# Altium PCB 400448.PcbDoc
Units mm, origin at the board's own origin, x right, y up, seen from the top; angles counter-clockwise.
Board outline 44.3 x 77.32 mm, 2 copper layers (Top Layer, Bottom Layer), stack 1.271 mm thick; 49 components, 38 nets, 169 pads, 325 vias.
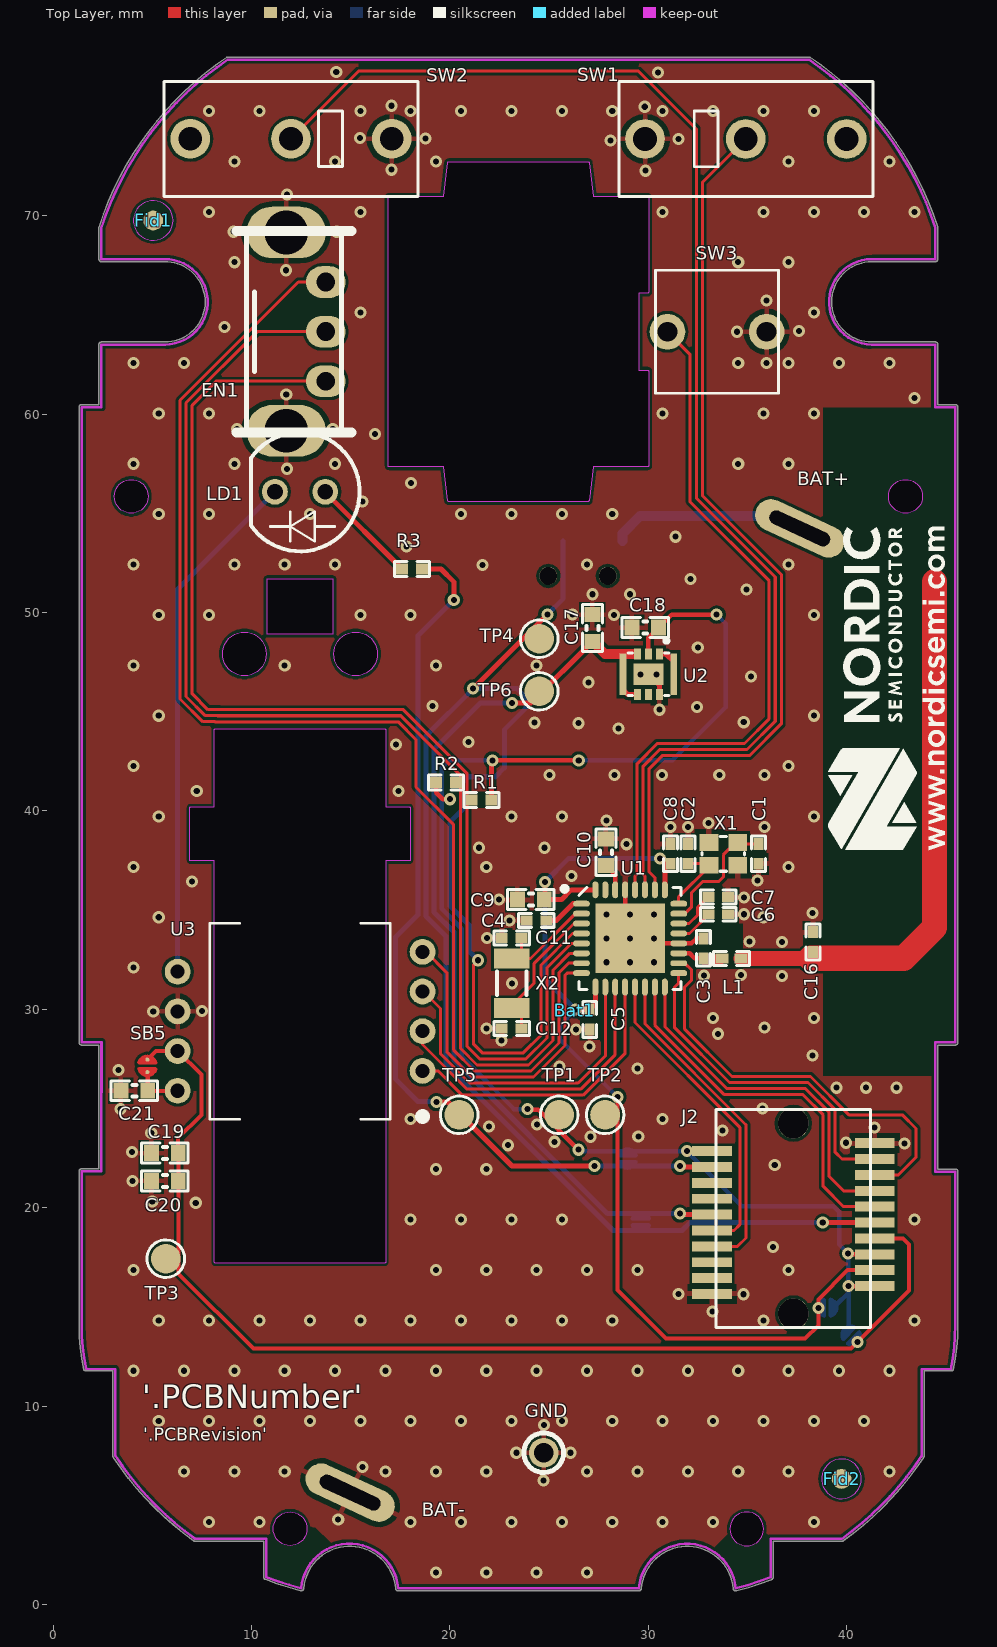
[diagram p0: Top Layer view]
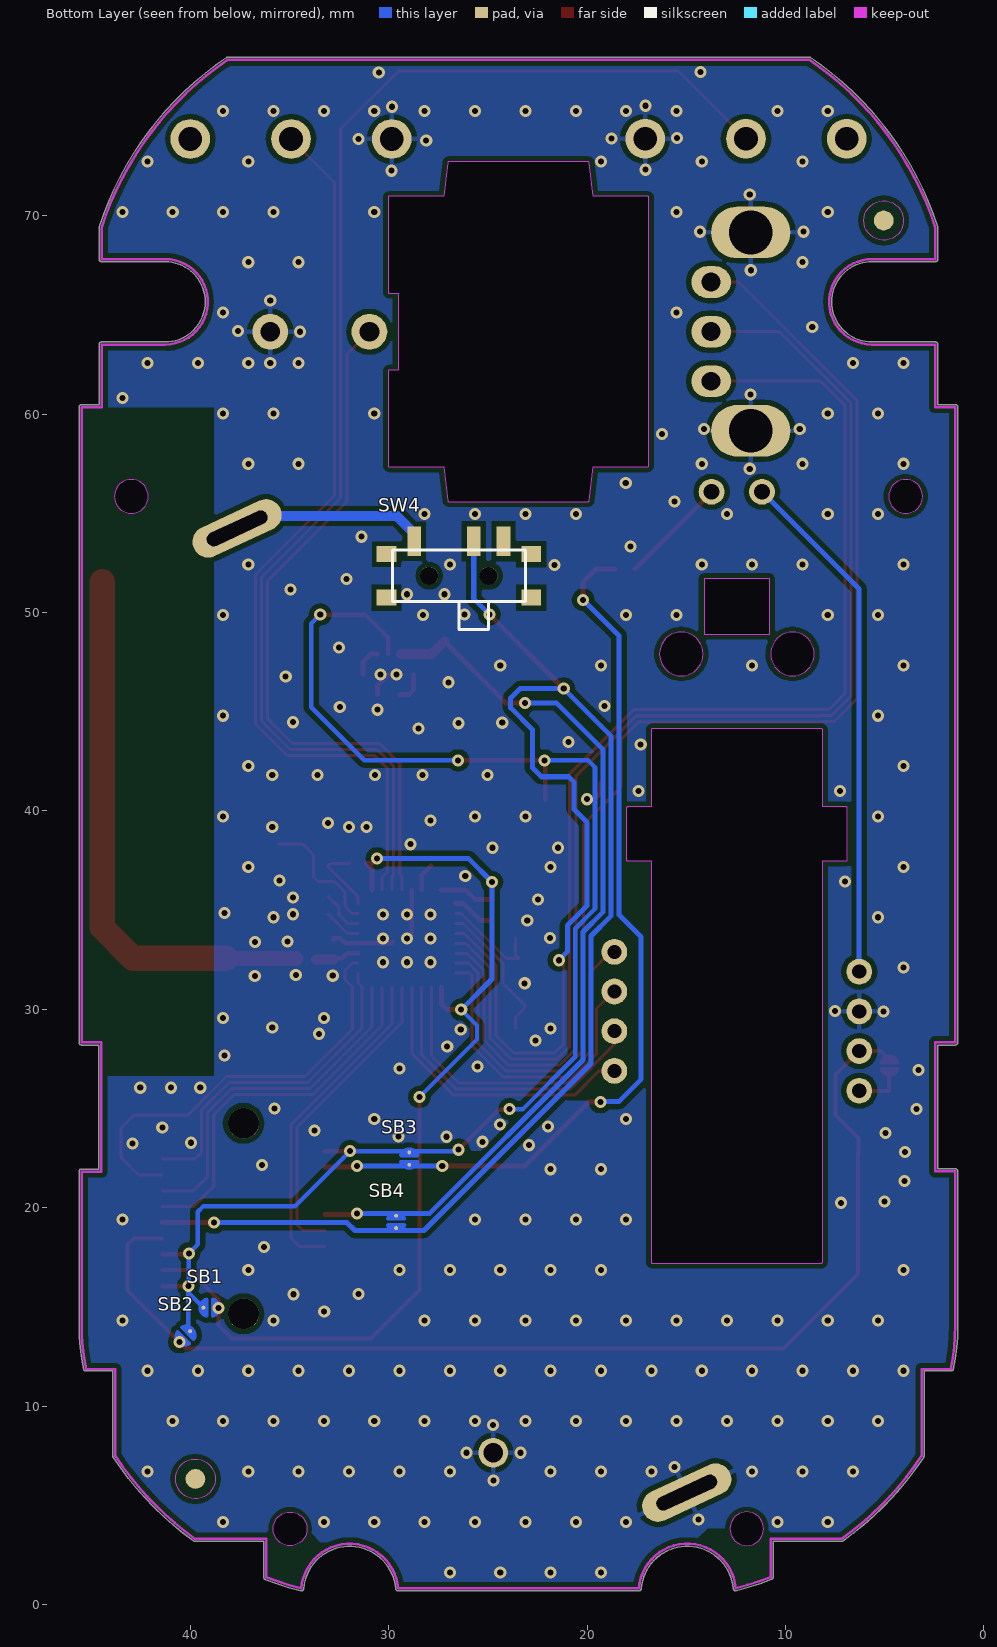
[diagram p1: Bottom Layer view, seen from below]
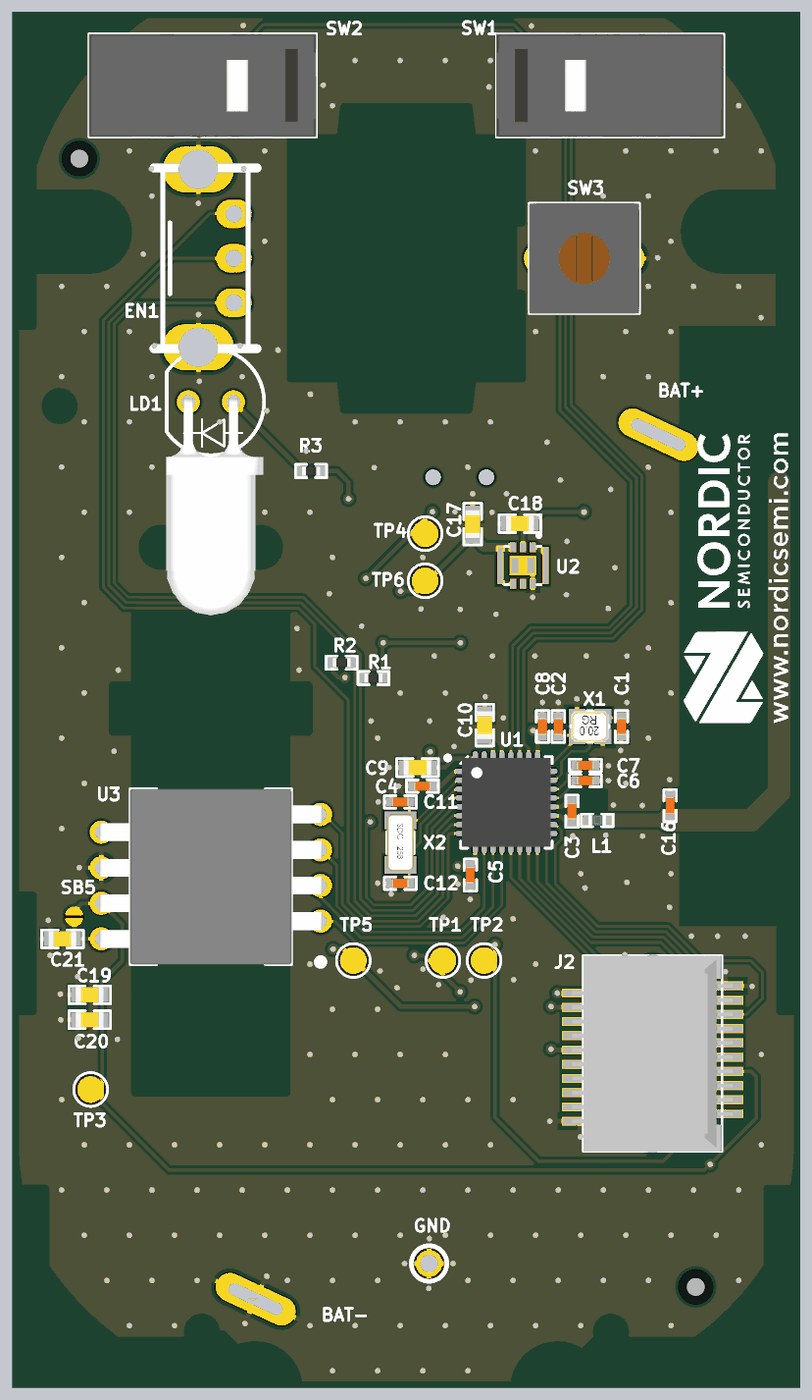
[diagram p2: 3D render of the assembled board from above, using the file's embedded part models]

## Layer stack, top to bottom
Top Solder: solder mask 0.0102, Solder Resist, Dk 3.5
Top Layer: signal copper 0.0356
Dielectric1: core 1.2, FR-4, Dk 4.8
Bottom Layer: signal copper 0.0356
Bottom Solder: solder mask 0.0102, Solder Resist, Dk 3.5

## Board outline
1.543,11.846 cw(c12.069,14.064) 1.312,14.064 1.312,21.831 cw(c1.439,21.831) 1.439,21.959 2.312,21.959 2.312,28.202 1.445,28.202 cw(c1.445,28.33) 1.344,28.251 cw(c1.439,28.336) 1.312,28.336 1.312,60.362 cw(c1.439,60.362) 1.439,60.489 2.312,60.489 2.312,63.514 cw(c2.44,63.514) 2.44,63.642 5.643,63.642 ccw(c5.643,65.666) 7.667,65.666 ccw(c5.643,65.666) 5.618,67.69 ccw(c5.643,65.666) 5.617,67.69 ccw(c5.616,67.753) 5.618,67.69 ccw(c5.616,67.753) 5.618,67.69 cw(c5.615,67.817) 5.617,67.69 cw(c5.615,67.817) 5.617,67.69 cw(c5.615,67.817) 5.617,67.69 cw(c5.643,65.666) 5.617,67.69 ccw(c5.616,67.753) 5.617,67.69 ccw(c5.643,65.666) 5.617,67.69 ccw(c5.643,65.666) 5.617,67.69 cw(c5.616,67.753) 5.617,67.69 cw(c5.615,67.753) 5.617,67.69 cw(c5.615,67.753) 5.616,67.689 cw(c5.616,67.753) 5.615,67.69 5.615,67.689 ccw(c5.616,67.753) 5.616,67.689 ccw(c5.616,67.753) 5.617,67.689 ccw(c5.615,67.817) 5.617,67.69 cw(c5.616,67.753) 5.617,67.69 cw(c5.616,67.753) 5.617,67.689 cw(c5.616,67.753) 5.616,67.689 cw(c5.615,67.753) 5.616,67.689 cw(c5.615,67.753) 5.615,67.689 2.44,67.689 cw(c2.44,67.817) 2.312,67.817 2.312,69.412 cw(c2.44,69.412) 2.319,69.452 cw(c17.952,64.365) 8.739,77.981 cw(c8.811,77.875) 8.811,78.003 38.103,78.003 cw(c38.103,77.875) 38.174,77.981 cw(c28.961,64.365) 44.595,69.452 cw(c44.473,69.412) 44.601,69.412 44.601,67.817 cw(c44.473,67.817) 44.473,67.69 41.271,67.689 cw(c41.271,67.753) 41.27,67.689 ccw(c41.271,65.666) 41.27,67.689 cw(c41.271,67.817) 41.27,67.689 ccw(c41.271,67.817) 41.271,67.689 cw(c41.27,67.753) 41.27,67.689 ccw(c41.271,65.666) 41.271,63.642 44.473,63.642 cw(c44.473,63.514) 44.601,63.514 44.601,60.489 45.474,60.489 cw(c45.474,60.362) 45.575,60.44 cw(c45.479,60.355) 45.607,60.355 45.607,28.33 cw(c45.479,28.33) 45.479,28.202 44.606,28.202 44.606,21.953 45.479,21.953 cw(c45.479,21.825) 45.607,21.825 45.607,14.058 cw(c45.543,14.058) 45.607,14.057 ccw(c34.848,14.058) 45.607,14.058 45.607,14.057 cw(c34.848,14.058) 45.376,11.839 cw(c45.313,11.852) 45.303,11.789 cw(c45.3,11.853) 45.3,11.789 43.906,11.789 43.906,7.483 cw(c43.778,7.483) 43.885,7.412 cw(c30.425,16.321) 39.834,3.206 cw(c39.76,3.31) 39.76,3.183 36.3,3.183 36.3,1.375 cw(c36.172,1.375) 36.218,1.255 cw(c30.425,16.321) 34.444,0.688 cw(c34.428,0.75) 34.428,0.686 cw(c34.412,0.748) 34.412,0.684 ccw(c34.412,0.812) 34.412,0.684 cw(c34.412,0.812) 34.285,0.802 cw(c34.412,0.812) 34.285,0.803 ccw(c34.348,0.807) 34.285,0.803 cw(c31.969,0.608) 34.285,0.802 cw(c31.969,0.608) 34.285,0.802 34.285,0.803 ccw(c31.969,0.608) 29.653,0.808 ccw(c31.969,0.608) 29.653,0.803 cw(c29.525,0.814) 29.51,0.687 17.394,0.687 cw(c17.394,0.815) 17.266,0.805 cw(c17.394,0.815) 17.266,0.805 cw(c14.95,0.615) 17.266,0.805 cw(c14.95,0.615) 17.266,0.805 ccw(c14.95,0.615) 12.634,0.809 ccw(c14.95,0.615) 12.634,0.809 ccw(c12.507,0.819) 12.634,0.809 cw(c12.507,0.819) 12.507,0.691 cw(c12.507,0.755) 12.491,0.693 cw(c12.491,0.757) 12.475,0.695 cw(c16.493,16.327) 10.701,1.262 cw(c10.747,1.381) 10.619,1.381 10.619,3.189 7.159,3.189 cw(c7.159,3.317) 7.084,3.213 cw(c16.493,16.327) 3.034,7.419 cw(c3.141,7.489) 3.013,7.489 3.013,11.795 1.625,11.795 cw(c1.625,11.859) 1.616,11.796 cw(c1.605,11.859)
cut-out: 15.25,46.816 cw(c15.25,47.917) 14.149,47.917 cw(c15.25,47.917) 15.25,49.018 cw(c15.25,47.917) 16.351,47.917 cw(c15.25,47.917)
cut-out: 3.941,55.007 cw(c3.941,55.858) 3.091,55.858 cw(c3.941,55.858) 3.941,56.709 cw(c3.941,55.858) 4.792,55.858 cw(c3.941,55.858)
cut-out: 19.891,55.65 19.691,57.345 16.952,57.345 cw(c16.952,57.409) 16.888,57.409 16.888,70.92 cw(c16.952,70.92) 16.952,70.984 19.691,70.984 19.891,72.679 cw(c19.954,72.671) 19.954,72.735 26.959,72.735 cw(c26.959,72.671) 27.023,72.679 27.222,70.984 29.962,70.984 cw(c29.962,70.92) 30.026,70.92 30.026,66.166 cw(c29.962,66.166) 29.962,66.102 29.525,66.102 29.525,62.227 29.962,62.227 cw(c29.962,62.163) 30.026,62.163 30.026,57.409 cw(c29.962,57.409) 29.962,57.345 27.222,57.345 27.023,55.65 cw(c26.959,55.658) 26.959,55.594 19.954,55.594 cw(c19.954,55.658)
cut-out: 9.646,46.816 cw(c9.646,47.917) 8.545,47.917 cw(c9.646,47.917) 9.646,49.018 cw(c9.646,47.917) 10.747,47.917 cw(c9.646,47.917)
cut-out: 8.131,17.268 8.131,37.48 6.944,37.48 cw(c6.944,37.544) 6.88,37.544 6.88,40.146 cw(c6.944,40.146) 6.944,40.21 8.131,40.21 8.131,44.089 cw(c8.195,44.089) 8.195,44.153 16.701,44.153 cw(c16.701,44.089) 16.765,44.089 16.765,40.21 17.952,40.21 cw(c17.952,40.146) 18.016,40.146 18.016,37.544 cw(c17.952,37.544) 17.952,37.48 16.765,37.48 16.765,17.268 cw(c16.701,17.268) 16.701,17.204 8.195,17.204 cw(c8.195,17.268)
cut-out: 34.12,3.811 ccw(c34.971,3.811) 34.971,2.96 ccw(c34.971,3.811) 35.822,3.811 ccw(c34.971,3.811) 34.971,4.661 ccw(c34.971,3.811)
cut-out: 11.948,2.966 cw(c11.948,3.817) 11.097,3.817 cw(c11.948,3.817) 11.948,4.668 cw(c11.948,3.817) 12.798,3.817 cw(c11.948,3.817)
cut-out: 42.972,55.007 cw(c42.972,55.858) 42.121,55.858 cw(c42.972,55.858) 42.972,56.709 cw(c42.972,55.858) 43.823,55.858 cw(c42.972,55.858)
cut-out: 10.797,48.913 10.797,51.715 14.099,51.715 14.099,48.913

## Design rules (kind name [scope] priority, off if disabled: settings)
Clearance ANT_Clerance [InNet('ANT')] p1: gap=0.127 ignorepadtopadclearanceinfootprint=FALSE except(0: Arc-Hole Track-Hole SMDPad-Hole THPad-Hole Via-Hole Fill-Hole Poly-Hole Region-Hole Text-Hole)
Clearance Polygon_Clearance [(InNamedPolygon('Top_Layer-GND')) or (InNamedPolygon('Bottom_Layer-GND'))] p2: gap=0.254 ignorepadtopadclearanceinfootprint=FALSE except(0: Arc-Hole Track-Hole SMDPad-Hole THPad-Hole Via-Hole Fill-Hole Poly-Hole Region-Hole Text-Hole)
Clearance [All] p3: gap=0.152 ignorepadtopadclearanceinfootprint=FALSE except(0: Arc-Hole Track-Hole SMDPad-Hole THPad-Hole Via-Hole Fill-Hole Poly-Hole Region-Hole Text-Hole)
ComponentClearance [All] p1 off: gap=0.254 collisioncheckmode=3 verticalgap=0.254 showdistances=FALSE
DiffPairsRouting [All] p1: maxlimit=0.15 minlimit=0.15 mostfreqgap=0.15 toplayer_minwidth=0.381 toplayer_maxwidth=0.381 toplayer_prefwidth=0.381 bottomlayer_minwidth=0.381 bottomlayer_maxwidth=0.381 bottomlayer_prefwidth=0.381 maxuncoupledlength=12.7
FabricationTestPointUsage TestPointUsage [All] p1: valid=0 allowmultiple=FALSE
FabricationTestpoint Testpoint [All] p1: side=3 testpointundercomponent=TRUE minsize=1.016 maxsize=2.54 preferedsize=1.524 minholesize=0 maxholesize=1.016 preferedholesize=0.813 testpointgrid=0.025 allowsidetop=TRUE allowsidebottom=TRUE usegrid=TRUE gridtolerance=0
Height [All] p1 off: minheight=0 maxheight=25.4 prefheight=12.7
HoleSize [All] p1: absolutevalues=TRUE maxlimit=5 minlimit=0.305 maxpercent=80.000 minpercent=20.000
MinimumAnnularRing [All] p1 off: minimumring=0.152
PolygonConnect PolygonConnect_1 [isVia and innet(gnd)] p1: connectstyle=Direct reliefconductorwidth=0.254 reliefentries=4 polygonreliefangle="90 Angle" airgapwidth=0.254
PolygonConnect [All] p2: connectstyle=Relief reliefconductorwidth=0.254 reliefentries=4 polygonreliefangle="90 Angle" airgapwidth=0.254
RoutingVias [All] p1: holewidth=0.305 width=0.61 viastyle="Through Hole" minholewidth=0.305 minwidth=0.61 maxholewidth=0.711 maxwidth=1.27
SilkToSolderMaskClearance SilkscreenOverComponentPads [IsPad] p1: minsilkscreentomaskgap=0.254 clearancetoexposedcopper=TRUE
SolderMaskExpansion [All] p1: expansion=0.076
Width [All] p1: maxlimit=2.54 minlimit=0.152 preferedwidth=0.152
23 further rules are at their usual default settings.

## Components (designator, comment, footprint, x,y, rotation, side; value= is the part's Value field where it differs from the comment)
Bat1 "" MORFFLUOA_Battery_Spring 26.308,29.943 r0 top locked
C1 "12pF" CAPC1005X04L 35.564,37.842 r270 top
C2 "12pF" CAPC1005X04L 32.008,37.842 r90 top
C3 "0.8pF" CAPC1005X04L 32.778,33.075 r270 top
C4 "100nF" CAPC1005X04L 24.363,34.489 r180 top
C5 "100nF" CAPC1005X04L 27.055,29.486 r270 top
C6 "N.C." CAPC1005X04L 33.532,34.794 r180 top
C7 "100pF" CAPC1005X04L 33.532,35.658 r0 top
C8 "100nF" CAPC1005X04L 31.119,37.842 r90 top
C9 "4.7µF" CAPC1608X06L 24.083,35.531 r180 top
C10 "1.0µF" CAPC1608X06L 27.868,37.918 r270 top
C11 "12pF" CAPC1005X04L 23.118,33.6 r180 top
C12 "12pF" CAPC1005X04L 23.118,29.028 r180 top
C16 "1.2pF" CAPC1005X04L 38.304,33.392 r90 top
C17 "10µF" CAPC1608X06L 27.19,49.222 r270 top
C18 "10µF" CAPC1608X06L 29.851,49.247 r0 top
C19 "10µF" CAPC1608X06L 5.633,22.756 r0 top
C20 "100nF" CAPC1608X06L 5.633,21.354 r0 top
C21 "4.7µF" CAPC1608X06L 4.098,25.896 r0 top
EN1 "Scroll wheel encoder" M01_Scroll_Wheel_Encoder 13.748,64.164 r270 top locked
Fid1 "Fiducial mark" Fiducial 5.048,69.766 r0 top
Fid2 "Fiducial mark" Fiducial 39.744,6.332 r0 top
GND "TP" TESTPAD-TH 24.733,7.649 r0 top
J2 "Card Edge, 0.8mm" 10056847-101LF 37.316,19.453 r90 top
L1 "3.9nH" INDC1005X04L 34.2,32.567 r0 top
LD1 "LED" LED_5MM_RA 12.452,56.09 r180 top locked
R1 "1M0" RESC1005X04L 21.601,40.56 r0 top
R2 "1M0" RESC1005X04L 19.811,41.432 r180 top
R3 "4R7" RESC1005X04L 18.093,52.202 r0 top
SB1 "Solderbridge" Solderbridge#1 39.026,14.961 r180 bottom
SB2 "Solderbridge" Solderbridge#1 40.236,13.554 r315 bottom
SB3 "Solderbridge" Solderbridge#1 28.964,22.477 r270 bottom
SB4 "Solderbridge" Solderbridge#1 29.626,19.283 r90 bottom
SB5 "Solderbridge" Solderbridge#2 4.752,27.152 r270 top
SW1 "SPDT" D2F-F 29.842,73.875 r0 top locked
SW2 "SPDT" D2F-F 17.072,73.882 r180 top locked
SW3 "EVQ-P0E07K" EVQP0E07K 33.471,64.157 r0 top locked
SW4 "CUS-12TB" CUS-12B 26.462,51.853 r180 bottom locked
TP1 "Ø1.5mm,SMD" TP_SMD_Ø1.5mm 25.513,24.683 r0 top
TP2 "Ø1.5mm,SMD" TP_SMD_Ø1.5mm 27.828,24.683 r0 top
TP3 "Ø1.5mm,SMD" TP_SMD_Ø1.5mm 5.685,17.433 r0 top
TP4 "Ø1.5mm,SMD" TP_SMD_Ø1.5mm 24.512,48.683 r0 top
TP5 "Ø1.5mm,SMD" TP_SMD_Ø1.5mm 20.472,24.683 r0 top
TP6 "Ø1.5mm,SMD" TP_SMD_Ø1.5mm 24.512,46.033 r0 top
U1 "nRF52810-QCAA" Nordic_QFN50P500X500X90-33N 29.087,33.575 r0 top locked
U2 "XCL101" CL-2025 30.014,46.889 r270 top
U3 "PAW3212" PAW3212DB-TJDT 12.454,28.899 r90 top locked
X1 "32MHz" BT-XTAL_2016 33.786,37.842 r180 top
X2 "32.768kHz" XTAL_3215 23.118,31.314 r270 top

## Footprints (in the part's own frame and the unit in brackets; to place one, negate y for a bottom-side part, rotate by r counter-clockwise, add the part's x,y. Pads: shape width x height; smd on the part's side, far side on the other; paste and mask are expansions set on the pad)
10056847-101LF [mm]
  rect 0.5x2 smd paste-0.05 mask+0.025: 1(-3.4,-4.1) 2(-2.6,-4.1) 3(-1.8,-4.1) 4(-1,-4.1) 5(-0.2,-4.1) 6(0.6,-4.1) 7(1.4,-4.1) 8(2.2,-4.1) 9(3,-4.1) 10(3.8,-4.1) 11(3.4,4.1) 12(2.6,4.1) 13(1.8,4.1) 14(1,4.1) 15(0.2,4.1) 16(-0.6,4.1) 17(-1.4,4.1) 18(-2.2,4.1) 19(-3,4.1) 20(-3.8,4.1)
  round 1.55 hole 1.55 unplated mask+0: ""(-4.8,0) ""(4.8,0)
  silkscreen extent -5.5,-3.9 5.5,3.9, body extent -5.5,-4.5 5.5,4.53, height 5.28
BT-XTAL_2016 [mm] "Crystal 2.0 x 1.6 mm"
  rect 0.95x0.85 smd: 1(-0.725,-0.575) 2(0.725,-0.575) 3(0.725,0.575) 4(-0.725,0.575)
  silkscreen extent -1.08,-0.88 1.08,0.88, body extent -1.05,-0.85 1.05,0.85, height 0.56
CAPC1005X04L [mm] "Chip Capacitor, 2-Leads, Body 1.0x0.5mm, IPC High Density"
  rect 0.6x0.5 smd: 1(-0.5,0) 2(0.5,0)
  silkscreen extent -0.9,-0.35 0.9,0.35, body extent -0.51,-0.25 0.51,0.25, height 0.5
CAPC1608X06L [mm] "Chip Capacitor, 2-Leads, Body 1.6x0.8mm, IPC High Density"
  rect 0.75x0.8 smd: 1(-0.675,0) 2(0.675,0)
  silkscreen extent -1.17,-0.5 1.17,0.5, body extent -0.8,-0.43 0.8,0.43, height 0.8
CL-2025 [mm]
  rect 0.55x0.35 smd paste-0.025 mask+0.076: 1(-1.025,0.55) 2(-1.025,0) 3(-1.025,-0.55) 4(1.025,-0.55) 5(1.025,0) 6(1.025,0.55)
  rect 2.1x0.35 smd paste-0.038 mask+0.076: 7(0,1.275) 8(0,-1.275)
  rect 1.1x1.5 smd paste-5 mask+0.076: 9(0,0)
  silkscreen extent -1.8,-1.02 1.07,1.02, body extent -1,-1.25 1.01,1.25, height 1
CUS-12B [mm] "Slide Switches - SPDT, SMD, ON-ON"
  rect 1x0.8 smd: 0(-3.65,-1.1) 0(-3.65,1.1) 0(3.65,-1.1) 0(3.65,1.1)
  round 0.9 hole 0.9 unplated: 0(-1.5,0) 0(1.5,0)
  rect 0.7x1.5 smd: 1(2.25,1.75) 2(0.75,1.75) 3(-2.25,1.75)
  silkscreen extent -3.35,-2.7 3.35,1.3, body extent -3.85,-2.75 3.85,2.2, height 1.4
D2F-F [mm]
  round 2 hole 1.2: 1(10.16,0) 2(0,0) 3(5.08,0)
  silkscreen extent -1.32,-2.9 11.48,2.9, body extent -1.32,-2.9 11.48,2.9, height 7
EVQP0E07K [mm]
  round 1.8 hole 1: 1(-2.5,0) 2(2.5,0)
  silkscreen extent -3.1,-3.1 3.1,3.1, body extent -3.1,-3.1 3.1,3.1, height 7.5
Fiducial [mm] "Fiducial Mark"
  round 1 smd paste+0 mask+0.5: 0(0,0)
  round 1 smd far side paste+0 mask+0.5: 0(0,0)
  Top Layer keep-out circle w0.01: c0,0 r1
  Bottom Layer keep-out circle w0.01: c0,0 r1
INDC1005X04L [mm] "Chip Inductor, 2-Leads, Body 1.0x0.5mm, IPC High Density"
  rect 0.65x0.5 smd: 1(-0.475,0) 2(0.475,0)
  silkscreen extent -0.9,-0.35 0.9,0.35, body extent -0.5,-0.3 0.5,0.3, height 0.5
LED_5MM_RA [mm]
  round 1.3 hole 0.8: 1(1.27,0) 2(-1.27,0)
  silkscreen extent -3,-3 2.48,3, body extent -2.95,-0.25 2.5,12, height 5.95
M01_Scroll_Wheel_Encoder [mm]
  oval 1.6x2 hole 0.95: 1(-2.5,0) 2(0,0) 3(2.5,0)
  oval 2.6x4 hole 2.2: 4(-5,-2) 5(5,-2)
  silkscreen extent -5.08,-4.5 5.08,1.3
MORFFLUOA_Battery_Spring [mm] "Edge Mount Battery Holder Suitable for 1xAAA"
  oval 4.8x1.6 hole 0.7 slot 3.3 at 155 deg rot 155: 1(11.333,24.304) 2(-11.333,-24.304)
Nordic_QFN50P500X500X90-33N [mm] "QFN32 5x5x0.85mm, 0.5mm pitch - Medium Density"
  oval 0.85x0.3 smd mask+0.076: 1(-2.45,1.75) 2(-2.45,1.25) 3(-2.45,0.75) 4(-2.45,0.25) 5(-2.45,-0.25) 6(-2.45,-0.75) 7(-2.45,-1.25) 8(-2.45,-1.75) 17(2.45,-1.75) 18(2.45,-1.25) 19(2.45,-0.75) 20(2.45,-0.25) 21(2.45,0.25) 22(2.45,0.75) 23(2.45,1.25) 24(2.45,1.75)
  oval 0.3x0.85 smd mask+0.076: 9(-1.75,-2.45) 10(-1.25,-2.45) 11(-0.75,-2.45) 12(-0.25,-2.45) 13(0.25,-2.45) 14(0.75,-2.45) 15(1.25,-2.45) 16(1.75,-2.45) 25(1.75,2.45) 26(1.25,2.45) 27(0.75,2.45) 28(0.25,2.45) 29(-0.25,2.45) 30(-0.75,2.45) 31(-1.25,2.45) 32(-1.75,2.45)
  rect 3.5x3.5 smd: 33(0,0)
  silkscreen extent -3.42,-2.57 2.57,2.62, body extent -2.5,-2.5 2.5,2.5, height 0.9
PAW3212DB-TJDT [mm] "Ultra Low Power Wireless Mouse Sensor"
  round 1.3 hole 0.71: 1(-2,-6.172) 2(0,-6.172) 3(2,-6.172) 4(4,-6.172) 5(3,6.172) 6(1,6.172) 7(-1,6.172) 8(-3,6.172)
  silkscreen extent -4.55,-6.42 5.45,4.55, body extent -4.45,-6.3 5.45,6.3, height 3.18
RESC1005X04L [mm] "Chip Resistor, 2-Leads, Body 1.0x0.5mm, IPC High Density"
  rect 0.6x0.55 smd: 1(-0.5,0) 2(0.5,0)
  silkscreen extent -0.87,-0.38 0.88,0.38, body extent -0.5,-0.25 0.5,0.25, height 0.3
Solderbridge#1 [mm]
  round 0.2 smd paste-10: 1(-0.312,0) 2(0.312,0)
  Top Layer region: 0.077,0.432 0.152,0.505 0.271,0.467 0.335,0.424 0.409,0.351 0.462,0.292 0.521,0.193 0.549,0.099 0.544,-0.122 0.518,-0.193 0.434,-0.33 0.351,-0.411 0.259,-0.469 0.157,-0.5 0.107,-0.483 0.077,-0.43
  Top Layer region: -0.077,-0.432 -0.152,-0.505 -0.271,-0.467 -0.335,-0.424 -0.409,-0.351 -0.462,-0.292 -0.521,-0.193 -0.549,-0.099 -0.544,0.122 -0.518,0.193 -0.434,0.33 -0.351,0.411 -0.259,0.469 -0.157,0.5 -0.107,0.483 -0.077,0.43
  Top Layer lines w0.152: 0.153,-0.431 ccw(c0.042,0) 0.153,0.431 ; -0.153,-0.431 cw(c-0.042,0) -0.153,0.431
Solderbridge#2 [mm]
  round 0.2 smd paste-10: 1(-0.312,0) 2(0.312,0)
  Top Layer region: 0.077,0.432 0.152,0.505 0.271,0.467 0.335,0.424 0.409,0.351 0.462,0.292 0.521,0.193 0.549,0.099 0.544,-0.122 0.518,-0.193 0.434,-0.33 0.351,-0.411 0.259,-0.469 0.157,-0.5 0.107,-0.483 0.077,-0.43
  Top Layer region: -0.077,-0.432 -0.152,-0.505 -0.271,-0.467 -0.335,-0.424 -0.409,-0.351 -0.462,-0.292 -0.521,-0.193 -0.549,-0.099 -0.544,0.122 -0.518,0.193 -0.434,0.33 -0.351,0.411 -0.259,0.469 -0.157,0.5 -0.107,0.483 -0.077,0.43
  Top Layer lines w0.152: 0.153,-0.431 ccw(c0.042,0) 0.485,-0.046 ccw(c0.042,0) 0.153,0.431 ; -0.153,-0.431 cw(c-0.042,0) -0.461,0.149 cw(c-0.042,0) -0.153,0.431
TESTPAD-TH [mm]
  round 1.5 hole 1: 1(0,0)
  silkscreen extent -1,-1 1,1
TP_SMD_Ø1.5mm [mm]
  round 1.5 smd paste-5: 1(0,0)
  silkscreen extent -0.95,-0.95 0.95,0.95
XTAL_3215 [mm] "XTAL SMD 3.2 x 1.5 mm"
  rect 1x1.8 smd: 1(-1.25,0) 2(1.25,0)
  silkscreen extent -0.6,-0.75 0.6,0.75, body extent -1.6,-0.75 1.6,0.75, height 0.81

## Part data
Bat1: library part "MORFFLOUA Battery Spring", "Battery Spring, 1xAA", Part number IPS=N.A.
C1 C2 C11 C12: library part C0402-12p, "Capacitor, NP0, ±2%"
C3: library part C0402-0.8p, "Capacitor, NP0, ±5%"
C4 C5 C8: library part C0402-100n, "Capacitor, X7R, ±10%"
C6: library part C0402-N.C., "Not mounted"
C7: library part C0402-100p, "Capacitor, NP0, ±5%"
C9: library part C0603-4µ7, "Capacitor, X5R, ±10%"
C10: library part C0603-1µ0, "Capacitor, X7R, ±10%"
C16: library part C0402-1.2p, "Capacitor, NP0, ±0.1pF", Part number IPS=00000005410
C17 C18 C19: library part C0603-10µ, "Capacitor, X5R, ±20%", Part number IPS=00000007785
C20: library part C0603-100n, "Chip Cap 0603", Part number IPS=N.A.
C21: library part C0603-4µ7, "Capacitor, X5R, ±10%", Part number IPS=00000007783
EN1: library part "M01_Scroll_wheel_encoder, 9mm", "Scroll wheel encoder, 9mm", Part number IPS=N.A.
Fid1 Fid2: library part Fid-Mark, "Fiducial Mark", Part number IPS=N.A.
GND: library part "Testpoint TH", "Testpoint, through hole", Part number IPS=N.A.
J2: library part 10056847-101LF, "0.8mm pitch, dual edge, right angle, SMD, card edge connector", Manufacturer=FCI, Part number IPS=N.A., Supplier Part Number 1=609-4943-1-ND
L1: library part L0402-3n9, "High frequency chip inductor ±5%"
LD1: library part 7383M-RNW3-APSB, "LED, Red, 5mm, Vf=2.0", Manufacturer=Everlight, Part number IPS=N.A.
R1 R2: library part R0402-1M0, "Resistor, ±1%, 0.063W", Part number IPS=00000006807
R3: library part R0402-4R7, "Resistor, ±1%, 0.063W", Part number IPS=N.A.
SB1 SB2 SB3 SB4 SB5: Part number IPS=N.A.
SW1 SW2: library part D2F-F, "SWITCH SNAP ACTION SPDT 1A 125V", Manufacturer=Omron, Part number IPS=N.A., Supplier Part Number 1=SW503-ND
SW3: "Switch tactile, SPST-NO, 0.05A, 30V", Manufacturer="Panasonic - ECG", Part number IPS=N.A., Supplier Part Number 1=P10843S-ND
SW4: "Low-profile slide switch, SPDT, ON-ON", Manufacturer="Copal Electronics Inc", Part number IPS=N.A., Supplier Part Number 1=563-1102-1-ND
TP1 TP2 TP3 TP4 TP5 TP6: library part TP_SMD_Ø1.5MM, "1.0mm circular SMD testpad", Manufacturer="Nordic Semiconductor", Part number IPS=N.A.
U1: library part nRF52810-QCAAD0, "Multi-protocol Bluetooth Low Energy, ANT and 2.4GHz proprietary system-on-chip", Manufacturer="Nordic Semiconductor", Part number IPS=N.A.
U2: library part XCL101A211ER-G, "Inductor Built-in Step-up “micro DC/DC” Converter, VOUT=2.1V, 100mA", Manufacturer="Torex Semiconductor", Part number IPS=N.A., Supplier Part Number 1=893-1206-1-ND
U3: library part PAW3212DB-TJDT, "Ultra Low Power Wireless Mouse Sensor", Manufacturer="Pixart Imaging inc", Part number IPS=N.A.
X1: library part XTAL_SMD2016_32MHz_8pF_General, "XTAL SMD 2016, 32MHz, Cl=8pF, Total Tol: ±40ppm"
X2: library part XTAL_SMD3215_32.768kHz_9pF_General, "XTAL SMD 3215, 32.768kHz, Cl=9pF, Total Tol: ±50ppm"

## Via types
v1: diameter 0.61, hole 0.305, Top Layer to Bottom Layer, tented both sides, 325 vias

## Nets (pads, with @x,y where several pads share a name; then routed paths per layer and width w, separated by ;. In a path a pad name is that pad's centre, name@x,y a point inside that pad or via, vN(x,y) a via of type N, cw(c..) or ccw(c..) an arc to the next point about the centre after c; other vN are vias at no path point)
ANT: C16.1 L1.2 | length 27.9
  Top Layer w0.762: L1.2@34.683,32.573 37.308,32.573 ; 37.308,32.572 38.304,32.573
  Top Layer w1.27: 38.19,32.573 42.879,32.573 44.439,34.132 44.439,51.554
BAT+: Bat1.1 SW4.3 | length 9.9
  Bottom Layer w0.508: SW4.3 28.712,53.985 29.591,54.864 37.023,54.864 Bat1.1@37.641,54.246
DEC1: C4.1 U1.1 | length 2.1
  Top Layer w0.254: C4.1 25.379,34.489 26.214,35.325 U1.1
DEC2: C6.2 U1.21 | length 1.9
  Top Layer w0.152: U1.21 32.08,33.825 C6.2@33.049,34.794
DEC3: C7.1 U1.22 | length 2.3
  Top Layer w0.152: U1.22 32.059,34.325 32.495,34.762 32.495,35.147 C7.1@33.032,35.683
DEC4: C10.2 U1.30 | length 1.4
  Top Layer w0.229: C10.2 28.337,36.774 U1.30
GND: Bat1.2 C1.2 C2.2 C3.1 C4.2 C5.2 C6.1 C7.2 C8.2 C9.2 C10.1 C11.2 C12.2 C16.2 C17.1 C18.1 C19.1 C20.1 C21.1 EN1.4 EN1.5 GND.1 J2.10 J2.20 SW1.2 SW2.2 SW3.2 U1.20 U1.29 U1.33 U2.6 U2.9 U3.6 X1.2 X1.4 | length 6.9
  Top Layer w0.229: U1.29 28.837,33.825 v1(29.087,33.575) ; U1.33@29.787,33.4 29.862,33.325 U1.20 32.183,33.325 32.433,33.575 C3.1 ; C3.1@32.778,33.515 C3.1@32.786,33.515
  Top Layer w0.254: U2.9 30.564,46.339 U2.6
  other v1: 19.298,1.622 21.838,1.622 24.378,1.622 26.918,1.622 7.868,4.162 10.408,4.162 18.028,4.162 20.568,4.162 23.108,4.162 25.648,4.162 28.188,4.162 30.728,4.162 33.268,4.162 38.348,4.162 14.375,4.277 24.715,6.25 6.598,6.702 9.138,6.702 11.678,6.702 16.758,6.702 19.298,6.702 21.838,6.702 26.918,6.702 29.458,6.702 31.998,6.702 34.538,6.702 37.078,6.702 42.158,6.702 15.6,6.933 23.35,7.65 26.082,7.65 24.747,9.05 5.328,9.242 7.868,9.242 10.408,9.242 12.948,9.242 15.488,9.242 18.028,9.242 20.568,9.242 23.108,9.242 25.648,9.242 28.188,9.242 30.728,9.242 33.268,9.242 35.808,9.242 38.348,9.242 40.888,9.242 4.058,11.782 6.598,11.782 9.138,11.782 11.678,11.782 14.218,11.782 16.758,11.782 19.298,11.782 21.838,11.782 24.378,11.782 26.918,11.782 29.458,11.782 31.998,11.782 34.538,11.782 37.078,11.782 39.618,11.782 42.158,11.782 5.328,14.322 7.868,14.322 10.408,14.322 12.948,14.322 15.488,14.322 18.028,14.322 20.568,14.322 23.108,14.322 25.648,14.322 28.188,14.322 35.808,14.322 43.428,14.322 33.25,14.775 31.527,15.65 34.799,15.638 4.058,16.862 19.298,16.862 21.838,16.862 24.378,16.862 26.918,16.862 29.458,16.862 37.078,16.862 36.282,18.025 18.028,19.402 20.568,19.402 23.108,19.402 25.648,19.402 43.428,19.402 7.193,20.25 5,20.309 4.008,21.342 19.298,21.942 21.838,21.942 36.38,22.15 3.975,22.8 22.933,23.152 42.917,23.229 39.975,23.275 25.269,23.325 27.093,23.578 29.5,23.6 4.95,23.775 33.75,23.885 41.414,24.053 21.975,24.1 24.389,24.201 18.028,24.482 30.728,24.482 3.4,24.975 35.753,25 39.5,26.05 40.975,26.05 42.525,26.05 3.3,26.944 29.458,27.022 25.53,27.115 38.275,27.681 27.05,28.122 22.6,28.425 33.515,28.769 26.369,28.979 21.842,29.029 35.869,29.079 33.268,29.562 38.348,29.562 5.05,29.901 7.5,29.925 23.143,31.314 36.75,31.675 32.821,31.695 34.683,31.729 4.058,32.102 27.887,32.375 29.087,32.375 30.287,32.375 36.736,33.4 35.107,33.423 27.887,33.575 30.287,33.575 21.872,33.6 23.016,34.489 5.328,34.642 35.808,34.642 27.887,34.775 29.087,34.775 30.287,34.775 34.827,34.794 38.275,34.85 22.483,35.531 34.827,35.632 7,36.453 35.513,36.496 26.141,36.725 4.058,37.182 21.838,37.182 37.078,37.182 21.467,38.147 24.769,38.147 28.909,38.325 31.119,39.188 32.008,39.188 35.869,39.188 33.049,39.392 27.893,39.519 5.328,39.722 23.108,39.722 25.648,39.722 38.348,39.722 7.243,41.016 17.418,41.016 25.023,41.805 28.3,41.805 30.687,41.805 33.583,41.805 35.869,41.805 4.058,42.262 37.078,42.262 17.296,43.35 20.942,43.48 28.5,44.15 26.488,44.424 24.275,44.45 34.817,44.475 5.328,44.802 38.348,44.802 30.564,45.105 32.465,45.25 19.125,45.3 26.995,46.488 35.192,46.775 29.614,46.889 30.414,46.889 4.058,47.342 11.678,47.342 19.298,47.342 24.378,47.342 32.5,48.25 5.328,49.882 7.868,49.882 15.488,49.882 18.028,49.882 28.275,49.882 38.348,49.882 26.189,49.913 27.19,50.926 29.087,50.926 34.958,51.166 32.125,51.7 21.65,52.4 4.058,52.422 9.138,52.422 11.678,52.422 14.218,52.422 26.918,52.422 37.078,52.422 17.816,53.325 31.375,53.825 5.328,54.962 7.868,54.962 12.948,54.962 20.568,54.962 23.108,54.962 25.648,54.962 28.188,54.962 15.6,55.591 18.05,56.525 11.8,57.25 4.058,57.502 9.138,57.502 14.218,57.502 34.538,57.502 37.078,57.502 16.228,59 9.278,59.25 14.099,59.25 5.328,60.042 7.868,60.042 30.728,60.042 35.808,60.042 38.348,60.042 43.428,60.825 11.755,61 4.058,62.582 6.598,62.582 34.538,62.582 35.971,62.582 37.078,62.582 39.618,62.582 42.158,62.582 34.475,64.157 37.6,64.2 8.65,64.4 15.488,65.122 38.348,65.122 35.971,65.736 11.748,67.257 9.138,67.662 34.538,67.662 37.078,67.662 9.1,69.2 14.302,69.2 7.868,70.202 15.488,70.202 30.728,70.202 35.808,70.202 38.348,70.202 40.888,70.202 43.428,70.202 11.8,71.075 29.865,72.275 17.05,72.325 9.138,72.742 14.218,72.742 19.298,72.742 37.078,72.742 42.158,72.742 28.108,73.8 31.525,73.872 18.775,73.9 15.475,73.925 7.868,75.282 10.408,75.282 15.488,75.282 18.028,75.282 20.568,75.282 23.108,75.282 25.648,75.282 28.188,75.282 30.728,75.282 33.268,75.282 35.808,75.282 38.348,75.282 29.825,75.5 17.05,75.55 30.5,77.225 14.275,77.25
NetC3_2: C3.2 L1.1 U1.19 | length 2.2
  Top Layer w0.229: U1.19 32.087,32.825 32.337,32.575 C3.2 ; C3.2@32.778,32.515 C3.2@32.786,32.515
  Top Layer w0.508: C3.2@32.778,32.52 L1.1@33.675,32.52
NetC21_2: C21.2 SB5.2 U3.8 | length 2.5
  Top Layer w0.203: 4.706,26.667 4.706,26.793 SB5.2 ; 4.773,26.692 C21.2 6.279,25.896 U3.8
NetLD1_1: LD1.1 U3.5 | length 26.2
  Bottom Layer w0.254: U3.5 6.282,51.19 LD1.1
NetLD1_2: LD1.2 R3.1 | length 5.5
  Top Layer w0.254: LD1.2 13.722,56.072 R3.1
NetU2_1: U2.1 U2.7 | length 1.5
  Top Layer w0.254: U2.1 30.895,47.914 31.289,47.52 U2.7
P0.00/XL1: C11.1 U1.2 X2.1 | length 5.3
  Top Layer w0.152: C11.1 23.618,32.76 23.423,32.564 24.066,32.564 26.327,34.825 U1.2
P0.01/XL2: C12.1 U1.3 X2.2 | length 7.2
  Top Layer w0.152: C12.1 23.618,29.59 23.143,30.064 23.143,30.222 24.25,31.329 24.25,32.317 26.258,34.325 U1.3
P0.04/AIN2: J2.5 SB4.1 SW4.2 TP4.1 U1.4 | length 88.5
  Top Layer w0.152: v1(21.425,32.475) 21.2,32.25 21.2,28.236 21.628,27.809 23.709,27.809 24.591,28.691 24.591,32.228 26.189,33.825 U1.4
  Top Layer w0.254: v1(21.175,46.175) 21.187,46.175 v1(24.925,49.913) ; v1(38.8,19.25) 39.499,19.25 39.502,19.253 J2.5
  Bottom Layer w0.254: v1(21.425,32.475) 20.994,32.906 20.994,34.226 20,35.22 20,39.425 20.65,40.075 20.65,41.45 20.925,41.725 22.3,41.725 22.75,42.175 22.75,44.1 23.85,45.2 23.85,45.7 23.375,46.175 v1(21.175,46.175) 21.175,46.163 18.8,43.788 18.8,34.7 19.8,33.7 19.8,27.275 28.222,18.853 31.703,18.853 32.1,19.25 v1(38.8,19.25) ; v1(24.925,49.913) 25.712,50.7 SW4.2
P0.05/AIN3: EN1.3 R1.1 U1.5 | length 61.6
  Top Layer w0.152: EN1.3 8.226,61.664 7.01,60.447 7.01,45.903 7.803,45.11 8.421,45.11 8.426,45.105 17.653,45.105 20.875,41.882 20.875,40.585 20.875,28.13 21.501,27.504 23.84,27.504 24.896,28.56 24.896,32.101 26.12,33.325 U1.5
P0.06: EN1.2 R2.1 U1.6 | length 63.4
  Top Layer w0.152: EN1.2 10.295,64.164 6.705,60.574 6.705,45.776 7.676,44.805 8.295,44.805 8.3,44.8 17.526,44.8 20.55,41.776 20.55,41.307 20.55,28.024 21.375,27.199 23.967,27.199 25.201,28.433 25.201,31.975 26.051,32.825 U1.6
P0.09: EN1.1 U1.7 | length 65.3
  Top Layer w0.152: EN1.1 12.364,66.664 6.4,60.7 6.4,45.65 7.55,44.5 8.169,44.5 8.174,44.495 17.4,44.495 18.3,43.595 18.3,41.2 20.175,39.325 20.175,27.968 21.249,26.894 24.093,26.894 25.506,28.307 25.506,31.849 25.982,32.325 U1.7
P0.10: U1.8 U3.4 | length 17.2
  Top Layer w0.152: U3.4 18.801,32.899 19.85,31.85 19.85,27.862 21.123,26.589 24.219,26.589 25.81,28.181 25.81,31.723 25.913,31.825 U1.8
P0.12: U1.10 U3.3 | length 16.5
  Top Layer w0.152: U3.3 18.67,30.899 19.525,30.044 19.525,27.756 20.996,26.285 26.472,26.285 27.837,27.649 U1.10
P0.14: U1.11 U3.2 | length 15.4
  Top Layer w0.152: U3.2 18.626,28.224 20.87,25.98 26.599,25.98 28.337,27.718 U1.11
P0.15: U1.12 U3.1 | length 14.9
  Top Layer w0.152: U3.1 19.401,26.899 20.625,25.675 26.725,25.675 28.837,27.787 U1.12
P0.16: J2.16 U1.13 | length 15.7
  Top Layer w0.152: U1.13 29.337,29.338 34.619,24.056 34.619,19.144 34.328,18.853 J2.16
P0.18: J2.17 U1.14 | length 16.7
  Top Layer w0.152: U1.14 29.837,29.269 34.906,24.2 34.925,24.2 34.925,18.476 34.502,18.053 J2.17
P0.20: J2.6 U1.15 | length 18.9
  Top Layer w0.152: U1.15 30.337,29.2 33.837,25.7 37.8,25.7 38.818,24.682 38.818,21.082 39.847,20.053 J2.6
P0.21: J2.7 U1.16 | length 17.9
  Top Layer w0.152: U1.16 30.837,29.138 33.97,26.005 37.926,26.005 39.123,24.808 39.123,21.577 39.847,20.853 J2.7
P0.25: SW1.3 U1.26 | length 45.9
  Top Layer w0.152: U1.26 30.337,36.642 30.052,36.927 30.052,42.135 30.708,42.79 35.103,42.79 36.71,44.397 36.71,51.921 32.73,55.901 32.73,71.683 SW1.3
P0.28/AIN4: SW2.3 U1.27 | length 68.4
  Top Layer w0.152: SW2.3 15.41,77.3 29.5,77.3 32.425,74.375 32.425,55.775 36.405,51.795 36.405,44.524 34.976,43.095 30.582,43.095 29.747,42.261 29.747,36.801 29.837,36.711 U1.27
P0.30/AIN6: SW3.1 U1.28 | length 35.6
  Top Layer w0.152: U1.28 29.337,36.721 29.443,36.826 29.443,42.387 30.455,43.4 34.85,43.4 36.1,44.65 36.1,51.6 32.099,55.601 32.099,63.029 SW3.1
SWDCLK: J2.9 U1.17 | length 16.9
  Top Layer w0.152: U1.17 31.537,31.325 31.337,31.125 31.337,29.069 34.096,26.31 38.05,26.31 ; 38.053,26.31 39.428,24.934 39.428,22.791 39.766,22.453 J2.9
SWDIO: J2.8 U1.18 | length 21.6
  Top Layer w0.152: U1.18 31.847,32.325 32.191,31.982 32.191,31.479 31.837,31.125 31.837,29 34.223,26.614 38.175,26.614 ; 38.179,26.614 40.111,24.683 42.811,24.683 43.5,23.993 43.5,22.543 42.611,21.653 J2.8
VBAT: C17.2 J2.15 SB4.2 TP6.1 U2.3 U2.4 U2.8 | length 46.9
  Top Layer w0.254: v1@22.95,45.475 22.975,45.45 v1(23.125,45.45) 24.094,45.45 C17.2 ; U2.8 28.739,46.109 28.984,45.864 U2.4 ; U2.3 U2.3@29.464,48.006 ; v1(31.6,19.7) 31.647,19.653 J2.15
  Top Layer w0.508: C17.2 27.824,47.914 U2.3@29.375,47.914
  Bottom Layer w0.254: v1(23.125,45.45) 21.55,45.45 19.206,43.106 19.206,34.9 20.206,33.9 20.206,27.443 27.95,19.7 29.386,19.7 29.866,19.7 v1(31.6,19.7)
VDD_LED: J2.12 R3.2 SB3.2 TP5.1 | length 45.9
  Top Layer w0.254: R3.2 18.595,52.2 19.554,52.2 20.2,51.554 v1(20.2,50.64) ; v1(19.327,25.327) 19.908,25.327 23.135,22.1 v1(27.3,22.1) ; v1(31.6,22.1) 31.647,22.053 J2.12
  Bottom Layer w0.254: v1(19.327,25.327) 19.303,25.35 18.4,25.35 17.272,26.478 17.272,33.647 18.394,34.769 18.394,48.833 v1(20.2,50.64) ; v1(27.3,22.1) 28.671,22.1 29.257,22.1 v1(31.6,22.1)
VDD_nRF: C5.1 C8.1 C9.1 J2.2 SB1.2 TP2.1 U1.9 U1.25 U1.32 | length 52.9
  Top Layer w0.203: v1(28.452,25.581) 28.452,15.848 30.9,13.4 37.9,13.4 38.575,14.075 38.575,15.375 40.053,16.853 J2.2
  Top Layer w0.254: v1(24.794,36.42) 24.794,35.567 C9.1 25.633,35.531 26.127,36.025 U1.32 ; v1(26.344,29.986) C5.1 27.337,30.268 U1.9 ; v1(30.586,37.614) 30.857,37.342 C8.1 30.837,37.06 U1.25
  Bottom Layer w0.203: v1(26.344,29.986) 26.344,29.981 25.55,29.187 25.55,28.483 v1(28.452,25.581)
  Bottom Layer w0.254: v1(26.344,29.986) 24.794,31.535 v1(24.794,36.42) 25.988,37.614 v1(30.586,37.614)
  other v1: 38.575,14.95
VDD_Sensor: C19.2 C20.2 J2.4 SB2.2 SB5.1 TP3.1 U3.7 | length 57.7
  Top Layer w0.203: SB5.1 4.901,27.613 5.187,27.899 U3.7 7.475,26.706 7.475,24.673 6.308,23.506 C19.2 ; C19.2@6.333,22.756 6.333,16.667 10.1,12.9 40.229,12.9 v1(40.554,13.225) 43.158,15.829 43.158,18.142 42.847,18.453 J2.4
VREG: C18.2 J2.1 J2.3 J2.11 R1.2 R2.2 SB1.1 SB2.1 SB3.1 TP1.1 U2.2 | length 77.3
  Top Layer w0.229: R2.2 19.311,40.925 19.644,40.593 v1(20,40.593) ; v1@19.926,40.674 v1@20,40.6 ; R1.2 22.101,42.501 v1(22.15,42.55) ; v1@22.25,42.55 v1(26.5,42.55) ; v1(23.909,24.975) 23.934,24.95 24.455,24.95 v1(26.48,22.925) ; U2.2 30.014,48.735 C18.2 31.181,49.902 v1(33.45,49.902) ; v1(31.95,22.85) 33.212,22.85 J2.11 ; v1(40.075,17.7) 40.122,17.653 J2.3 ; v1(40.1,16.05) 40.103,16.053 J2.1
  Bottom Layer w0.229: v1(20,40.593) 19.607,40.593 19.6,40.6 ; v1(22.15,42.55) 19.95,42.55 19.6,42.2 19.6,40.6 ; v1(23.909,24.975) 23.232,24.975 20.6,27.606 20.6,34.063 19.6,35.063 19.6,40.6 ; v1(26.48,22.925) 26.48,22.87 26.5,22.85 v1(31.95,22.85) 34.734,20.066 39.359,20.066 39.625,19.8 39.625,18.15 v1(40.075,17.7) 40.075,16.075 v1(40.1,16.05) 40.1,15.722 ; v1(26.5,42.55) 31.225,42.55 33.9,45.225 33.9,49.452 v1(33.45,49.902) ; 39.488,15.11 40.1,15.722 ; SB2.1@39.997,13.793 40.1,13.896 40.1,15.722
XC1: C1.1 U1.23 X1.1 | length 6.6
  Top Layer w0.152: U1.23 31.847,34.825 32.191,35.168 32.191,35.886 32.749,36.445 33.557,36.445 33.786,36.674 33.786,37.791 34.337,38.342 C1.1
XC2: C2.1 U1.24 X1.3 | length 3.7
  Top Layer w0.152: U1.24 31.537,35.669 33.061,37.193 X1.3@33.061,37.195 ; C2.1@31.957,37.342 C2.1 32.914,37.342 X1.3@33.061,37.195 ; X1.3 X1.3@33.061,37.195
pads on no net: Fid1.0 Fid2.0 J2. J2.13 J2.14 J2.18 J2.19 SW1.1 SW2.1 SW4.0 SW4.1 U1.31 U2.5

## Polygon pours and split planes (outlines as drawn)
GND on Top Layer "Top Layer-GND" (solid, remove dead copper, pour order 41): 1.439,14.626 1.439,21.831 2.44,21.831 2.44,28.336 1.439,28.336 1.439,60.362 2.44,60.362 2.44,63.514 5.643,63.514 ccw(c5.643,65.666) 5.615,67.817 2.44,67.817 2.44,69.412 cw(c17.952,64.365) 8.811,77.875 38.103,77.875 cw(c28.961,64.365) 44.473,69.412 44.473,67.817 41.271,67.817 ccw(c41.271,65.666) 41.271,63.514 44.473,63.514 44.473,60.362 45.474,60.362 45.474,28.336 45.474,0.815 17.394,0.815 ccw(c14.95,0.615) 12.507,0.819 cw(c16.493,16.327) 10.747,1.381 10.747,3.317 7.159,3.317 cw(c16.494,16.327) 3.141,7.489 3.141,11.323 1.784,11.323 cw(c17.452,14.626)
GND on Bottom Layer "Bottom_Layer-GND" (solid, remove dead copper, pour order 42): 1.439,14.626 1.439,21.831 2.44,21.831 2.44,28.336 1.439,28.336 1.439,60.362 2.44,60.362 2.44,63.514 5.643,63.514 ccw(c5.643,65.666) 5.615,67.817 2.44,67.817 2.44,69.412 cw(c17.952,64.365) 8.811,77.875 38.103,77.875 cw(c28.961,64.365) 44.473,69.412 44.473,67.817 41.271,67.817 ccw(c41.271,65.666) 41.271,63.514 44.473,63.514 44.473,60.362 45.474,60.362 45.474,28.336 45.474,0.815 17.394,0.815 ccw(c14.95,0.615) 12.507,0.819 cw(c16.493,16.327) 10.747,1.381 10.747,3.317 7.159,3.317 cw(c16.494,16.327) 3.141,7.489 3.141,11.323 1.784,11.323 cw(c17.452,14.626)

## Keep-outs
Keep-Out Layer:
  lines w0.013: 1.439,14.626 1.439,21.831 2.44,21.831 2.44,28.336 1.439,28.336 1.439,60.362 2.44,60.362 2.44,63.514 5.643,63.514 ccw(c5.643,65.666) 5.615,67.817 2.44,67.817 2.44,69.412 cw(c17.952,64.365) 8.811,77.875 38.103,77.875 cw(c28.961,64.365) 44.473,69.412 44.473,67.817 41.271,67.817 ccw(c41.271,65.666) 41.271,63.514 44.473,63.514 44.473,60.362 45.474,60.362 45.474,28.336 44.473,28.336 ; 3.141,11.323 3.141,7.489 ccw(c16.493,16.327) 7.159,3.317 10.747,3.317 10.747,1.381 ccw(c16.493,16.327) 12.507,0.819 cw(c14.95,0.615) 17.394,0.815 22.456,0.815
  lines w0.127: 1.439,14.626 1.439,21.831 ; 1.445,60.355 1.445,28.33 2.446,28.33 2.446,25.828 ; 1.67,11.864 cw(c12.144,14.072) 1.439,14.072 1.439,21.831 ; 1.675,11.859 3.141,11.859 ; 3.141,11.823 3.141,7.489 ; 22.454,0.815 29.519,0.815 ; 29.525,0.814 cw(c31.969,0.608) 34.412,0.812 ccw(c30.425,16.321) 36.172,1.375 36.172,3.31 39.76,3.31 ccw(c30.425,16.321) 43.778,7.483 43.778,11.853 45.248,11.853 ccw(c34.73,14.071) 45.479,14.071 45.479,21.825 44.479,21.825 44.479,28.33 45.479,28.33 45.479,60.355 ; 45.474,28.336 45.474,60.362 ; 1.439,21.831 2.44,21.831 ; 1.439,21.831 2.44,21.831 ; 1.439,28.336 1.439,60.362 ; 1.439,28.336 2.44,28.336 ; 1.439,28.336 1.439,60.362 ; 1.439,28.336 2.44,28.336 ; 1.439,60.362 2.44,60.362 ; 1.439,60.362 2.44,60.362 ; 2.44,21.831 2.44,28.336 ; 2.44,21.831 2.44,28.336 ; 2.44,60.362 2.44,63.514 ; 2.44,60.362 2.44,63.514 ; 2.44,63.514 5.643,63.514 ; 2.44,63.514 5.643,63.514 ; 2.44,67.817 2.44,69.412 ; 2.44,67.817 5.615,67.817 ; 2.44,67.817 2.44,69.412 ; 2.44,67.817 5.615,67.817 ; 2.44,69.412 cw(c17.952,64.365) 8.811,77.875 ; 2.44,69.412 cw(c17.952,64.365) 8.811,77.875 ; 3.141,7.489 ccw(c16.493,16.327) 7.159,3.317 ; 3.141,7.489 ccw(c16.493,16.327) 7.159,3.317 ; 5.615,67.817 cw(c5.643,65.666) 5.643,63.514 ; 5.615,67.817 cw(c5.643,65.666) 5.643,63.514 ; 7.159,3.317 7.159,3.317 ; 7.159,3.317 10.747,3.317 ; 7.159,3.317 10.747,3.317 ; 8.811,77.875 38.103,77.875 ; 8.811,77.875 38.103,77.875 ; 10.747,1.381 ccw(c16.493,16.327) 12.507,0.819 ; 10.747,1.381 ccw(c16.493,16.327) 12.507,0.819 ; 10.747,1.381 10.747,3.317 ; 10.747,1.381 10.747,3.317 ; 12.507,0.819 cw(c14.95,0.615) 17.394,0.815 ; 12.507,0.819 cw(c14.95,0.615) 17.394,0.815 ; 12.507,0.819 12.507,0.819 ; 17.394,0.815 22.456,0.815 17.394,0.815 ; 38.103,77.875 cw(c28.961,64.365) 44.473,69.412 ; 38.103,77.875 cw(c28.961,64.365) 44.473,69.412 ; 41.271,63.514 cw(c41.271,65.666) 41.271,67.817 ; 41.271,63.514 cw(c41.271,65.666) 41.271,67.817 ; 41.271,63.514 44.473,63.514 ; 41.271,63.514 44.473,63.514 ; 41.271,67.817 41.271,67.817 ; 41.271,67.817 44.473,67.817 ; 41.271,67.817 44.473,67.817 ; 44.473,60.362 45.474,60.362 ; 44.473,60.362 44.473,63.514 ; 44.473,60.362 45.474,60.362 ; 44.473,60.362 44.473,63.514 ; 44.473,67.817 44.473,69.412 ; 44.473,67.817 44.473,69.412

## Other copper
Top Layer:
  pour cut-out: 34.802,32.025 32.059,32.025 32.059,34.337 34.802,34.337
  pour cut-out: 12.75,3.904 13.221,3.904 14.375,2.75 14.05,2.425 13.35,2.425 12.175,3.6
  pour cut-out: 34.119,3.675 33.119,2.675 32.85,2.675 32.85,2.625 33.35,2.125 34.65,3.425 34.922,3.425
  pour cut-out: 14.525,66.025 14.475,65.975 14.475,64.739 13.907,64.739 13.746,64.9 13.775,64.929 13.775,66.183
Bottom Layer:
  pour cut-out: 19.825,25.425 21,25.425 21.175,25.6 20.875,25.9 19.85,25.9 19.625,25.675
  pour cut-out: 25.953,23 25.803,22.85 25.321,22.85 25.321,22.8 25.775,22.346 26.054,22.625 26.15,22.625
  pour cut-out: 19.5,26.925 20.05,27.475 19.925,27.475 19.775,27.625 19.375,27.225 19.375,27.2
  pour cut-out: 32.775,3.15 33.45,3.15 34.3,4 34.725,3.575 34.725,3.05 33.702,3.05 32.827,2.175
  pour cut-out: 14.6,3.175 13.925,3.85 12.711,3.85 12.711,3.785 12.526,3.6 13.651,2.475 14.325,2.475
Multi-Layer:
  pour cut-out: 38.803,60.355 46.515,60.355 46.487,26.621 38.806,26.621

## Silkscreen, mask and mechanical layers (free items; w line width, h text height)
Top Overlay:
  drawing of 43 lines, arcs and shapes, not listed
  text "'.PCBNumber'" at 4.5,9.486 h2.03
  text "'.PCBRevision'" at 4.551,8.266 h0.64
Board Outline:
  circle w0.127: c34.971,3.811 r0.851
  circle w0.127: c15.25,47.917 r1.101
  circle w0.127: c9.646,47.917 r1.101
  circle w0.127: c11.948,3.817 r0.851
  circle w0.127: c3.941,55.858 r0.851
  circle w0.127: c42.972,55.858 r0.851
  lines w0.127: 1.605,11.859 cw(c12.069,14.064) 1.375,14.064 1.375,21.831 cw(c1.439,21.831) 1.439,21.895 2.376,21.895 2.376,28.266 1.445,28.266 cw(c1.445,28.33) 1.393,28.292 cw(c1.439,28.336) 1.375,28.336 1.375,60.362 cw(c1.439,60.362) 1.439,60.425 2.376,60.425 2.376,63.514 cw(c2.44,63.514) 2.44,63.578 5.643,63.578 ccw(c5.643,65.666) 7.731,65.666 ; 1.625,11.859 3.077,11.859 3.077,7.489 ccw(c3.141,7.489) 3.087,7.454 ccw(c16.493,16.327) 7.122,3.265 ccw(c7.159,3.317) 7.159,3.253 10.683,3.253 10.683,1.381 ccw(c10.747,1.381) 10.724,1.321 ccw(c16.493,16.327) 12.491,0.757 ; 12.507,0.755 ccw(c12.507,0.819) 12.57,0.814 cw(c14.95,0.615) 17.33,0.81 ; 34.428,0.75 ccw(c30.425,16.321) 36.195,1.315 ccw(c36.172,1.375) 36.236,1.375 36.236,3.246 39.76,3.246 ; 45.3,11.853 43.842,11.853 43.842,7.483 ; 45.313,11.852 ccw(c34.848,14.058) 45.543,14.058 45.543,21.825 ccw(c45.479,21.825) 45.479,21.889 44.542,21.889 44.542,28.266 45.479,28.266 ccw(c45.479,28.33) 45.543,28.33 45.543,60.355 ccw(c45.479,60.355) 45.526,60.399 ccw(c45.474,60.362) 45.474,60.425 44.537,60.425 44.537,63.514 ccw(c44.473,63.514) 44.473,63.578 41.271,63.578 cw(c41.271,65.666) 41.27,67.753 ; 2.376,69.412 cw(c2.44,69.412) 2.379,69.432 ; 2.376,69.412 cw(c2.44,69.412) 2.379,69.432 ; 2.376,69.412 2.376,67.817 ccw(c2.44,67.817) 2.44,67.753 5.615,67.753 ; 2.379,69.432 cw(c17.952,64.365) 8.775,77.928 ; 5.615,67.753 ccw(c5.615,67.817) 5.616,67.753 ; 5.615,67.753 ccw(c5.615,67.817) 5.616,67.753 ; 5.616,67.753 ccw(c5.643,65.666) 5.616,67.753 ; 5.616,67.753 cw(c5.643,65.666) 7.731,65.666 ; 5.616,67.753 ccw(c5.643,65.666) 5.616,67.753 ; 5.616,67.753 cw(c5.643,65.666) 7.731,65.666 ; 5.616,67.753 5.616,67.753 ; 5.616,67.753 5.616,67.753 ; 8.775,77.928 cw(c8.811,77.875) 8.811,77.939 ; 8.775,77.928 cw(c8.811,77.875) 8.811,77.939 ; 8.775,77.928 8.775,77.928 ; 8.775,77.928 8.775,77.928 ; 8.811,77.939 38.103,77.939 ; 17.33,0.81 ccw(c17.394,0.815) 17.394,0.751 29.515,0.751 ccw(c29.525,0.814) 29.589,0.808 ; 17.33,0.81 17.33,0.81 ; 29.589,0.808 cw(c31.969,0.608) 34.348,0.807 ; 29.589,0.808 29.589,0.808 ; 34.348,0.807 ccw(c34.412,0.812) 34.412,0.748 ; 34.348,0.807 34.348,0.807 ; 34.412,0.748 34.412,0.748 ; 38.103,77.939 cw(c38.103,77.875) 38.139,77.928 ; 38.103,77.939 cw(c38.103,77.875) 38.139,77.928 ; 38.139,77.928 cw(c28.961,64.365) 44.534,69.432 ; 38.139,77.928 38.139,77.928 ; 38.139,77.928 38.139,77.928 ; 39.76,3.246 ccw(c39.76,3.31) 39.797,3.258 ; 39.76,3.246 ccw(c39.76,3.31) 39.797,3.258 ; 39.797,3.258 ccw(c30.425,16.321) 43.831,7.447 ; 41.27,67.753 ccw(c41.271,67.817) 41.271,67.753 ; 41.27,67.753 ccw(c41.271,67.817) 41.271,67.753 ; 41.271,67.753 44.473,67.753 ccw(c44.473,67.817) 44.537,67.817 44.537,69.412 ; 43.831,7.447 ccw(c43.778,7.483) 43.842,7.483 ; 43.831,7.447 ccw(c43.778,7.483) 43.842,7.483 ; 44.534,69.432 cw(c44.473,69.412) 44.537,69.412 ; 44.534,69.432 cw(c44.473,69.412) 44.537,69.412 ; 6.944,37.544 6.944,40.146 8.195,40.146 8.195,44.089 16.701,44.089 16.701,40.146 17.952,40.146 17.952,37.544 16.701,37.544 16.701,17.268 8.195,17.268 8.195,37.544 6.944,37.544 ; 10.797,48.913 14.099,48.913 14.099,51.715 10.797,51.715 10.797,48.913 ; 16.952,57.409 16.952,70.92 19.748,70.92 19.954,72.671 26.959,72.671 27.166,70.92 29.962,70.92 29.962,66.166 29.461,66.166 29.461,62.163 29.962,62.163 29.962,57.409 27.166,57.409 26.959,55.658 19.954,55.658 19.748,57.409 16.952,57.409
Bottom Component Info:
  drawing of 267 lines, arcs and shapes, not listed
Bottom Assembly:
  circle w0.013: c40,73.872 r0.55
  circle w0.013: c29.832,73.872 r0.55
  circle w0.013: c34.916,73.872 r0.55
  circle w0.013: c17.082,73.872 r0.55
  circle w0.013: c6.914,73.872 r0.55
  circle w0.013: c11.998,73.872 r0.55
  circle w0.013: c13.749,66.667 r0.5
  circle w0.013: c13.749,64.165 r0.5
  circle w0.013: c13.749,61.663 r0.5
  circle w0.013: c11.747,68.668 r0.5
  circle w0.013: c11.747,59.661 r0.5
  circle w0.013: c6.271,25.894 r0.4
  circle w0.013: c6.271,31.899 r0.4
  circle w0.013: c6.271,29.898 r0.4
  circle w0.013: c6.271,27.896 r0.4
  circle w0.013: c18.625,26.895 r0.4
  circle w0.013: c18.625,28.897 r0.4
  circle w0.013: c18.625,30.898 r0.4
  circle w0.013: c18.625,32.9 r0.4
  circle w0.013: c13.639,56.089 r0.356
  circle w0.013: c11.257,56.089 r0.356
  circle w0.013: c24.958,51.855 r0.45
  circle w0.013: c27.96,51.855 r0.45
  circle w0.013: c36.007,64.165 r0.4
  circle w0.013: c30.923,64.165 r0.4
  lines w0.013: 3.025,68.861 2.494,69.123 3.287,70.862 3.877,70.571 ; 11.254,3.417 7.168,3.417 6.478,4.217 11.254,4.217 ; 11.547,3.124 11.547,1.239 12.348,0.996 12.348,3.124 ; 16.893,36.793 16.866,35.411 18.89,34.143 19.915,33.501 ; 34.571,3.117 34.571,0.99 35.371,1.233 35.371,3.117 ; 35.664,3.41 39.751,3.41 40.441,4.211 35.664,4.211 ; 43.036,70.571 43.656,70.877 44.45,69.138 43.888,68.861 ; 7.794,56.617 15.761,56.606 15.739,49.515 16.863,49.518 16.853,53.288 16.838,57.682 7.794,57.67 7.794,56.617 ; 13.652,5.865 cw(c13.8,6.182) 13.948,6.5 16.307,5.4 cw(c16.159,5.082) 16.011,4.765 13.652,5.865 ; 23.056,46.358 23.857,46.358 23.857,47.959 23.056,47.959 23.056,46.358 ; 36.323,54.481 cw(c36.471,54.798) 36.619,55.116 38.977,54.016 cw(c38.829,53.699) 38.681,53.381 36.323,54.481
